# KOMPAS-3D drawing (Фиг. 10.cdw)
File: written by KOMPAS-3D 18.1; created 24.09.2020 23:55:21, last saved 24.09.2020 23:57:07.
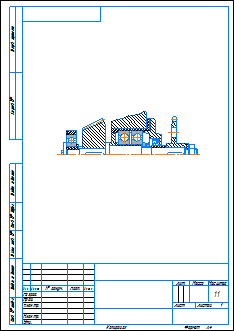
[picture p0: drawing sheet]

Sheet 1: A4, portrait

Document properties: Автор: user; Полное имя файла: C:\Users\user\Desktop\Задания\Фиг. 6.cdw

Title block, sheet 1: scale: 1:1; Количество листов документа: 1; Форматы листов документа: A4

Dimensions and other numbers on the sheet: 1:1; 1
